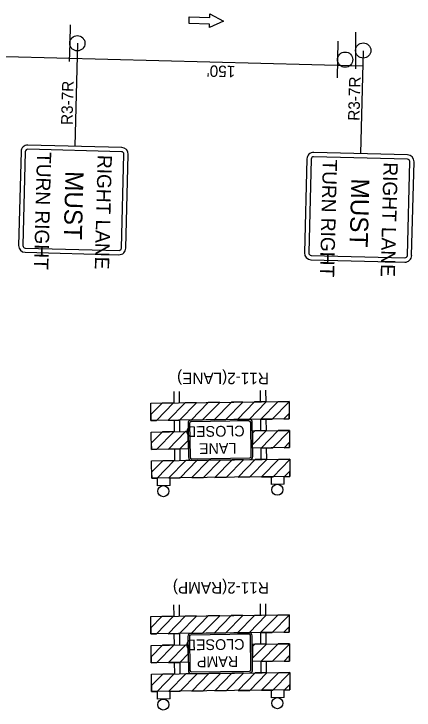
# Model space of a CAD drawing. Extents: x 2135767 to 2151731, y 141839 to 175894.
# Drawn here: x 2150438.8 to 2150648.7, y 145249 to 145614 of the extents above; entities that cross this region are included whole.
import ezdxf

# ---------------------------------------------------------------- set-up
doc = ezdxf.new("R2010")
doc.units = 0
for name, color, linetype in [('PR_Dimensions_Phase1', 7, 'Continuous'), ('PR_Phasing_Detour_1', 7, 'Continuous'), ('PR_Phasing_Traffic_Control_Devices_1', 7, 'Continuous'), ('Pr_Traffic_Arrows_Phase_1', 7, 'Continuous'), ('PR_Txt_Phase_1', 7, 'Continuous')]:
    doc.layers.add(name, color=color, linetype=linetype)

msp = doc.modelspace()

# ---------------------------------------------------------------- linework, layer by layer
at = {"layer": 'PR_Dimensions_Phase1'}
for p, q in [((2150472.1, 145598.57), (2150470.77, 145544.59)), ((2150622.05, 145594.7), (2150620.72, 145540.72))]:
    msp.add_line(p, q, dxfattribs=at)
msp.add_lwpolyline([(2150621.85, 145586.62), (2150300.64, 145594.91), (2150294.97, 145605.06), (2150288.79, 145585.47), (2150285.1, 145595.31), (2150279.06, 145595.47), (2150241.43, 145596.44)], dxfattribs=at)
at = {"layer": 'PR_Phasing_Detour_1'}
for p, q in [((2150608.74, 145599.72), (2150608.56, 145590.07)), ((2150608.56, 145590.07), (2150608.38, 145580.43))]:
    msp.add_line(p, q, dxfattribs=at)
msp.add_circle((2150612.56, 145590), 4, dxfattribs=at)
at = {"layer": 'PR_Phasing_Traffic_Control_Devices_1'}
for p, q in [((2150468.34, 145608.32), (2150468.1, 145598.67)), ((2150618.06, 145604.45), (2150618.06, 145594.8)), ((2150468.1, 145598.67), (2150467.86, 145589.03)), ((2150618.06, 145594.8), (2150618.06, 145585.15)), ((2150442.56, 145541.8), (2150441.29, 145492.6)), ((2150495.31, 145541.71), (2150446.11, 145542.98)), ((2150495.37, 145543.96), (2150446.16, 145545.23)), ((2150444.81, 145541.74), (2150443.54, 145492.54)), ((2150495.27, 145491.21), (2150496.54, 145540.41)), ((2150497.52, 145491.15), (2150498.79, 145540.35)), ((2150645.26, 145537.84), (2150596.06, 145539.11)), ((2150645.32, 145540.08), (2150596.11, 145541.35)), ((2150592.51, 145537.93), (2150591.24, 145488.73)), ((2150594.76, 145537.87), (2150593.49, 145488.67)), ((2150645.22, 145487.34), (2150646.49, 145536.54)), ((2150647.47, 145487.28), (2150648.74, 145536.48)), ((2150444.77, 145491.24), (2150493.97, 145489.97)), ((2150444.71, 145489), (2150493.91, 145487.72)), ((2150594.72, 145487.37), (2150643.92, 145486.1)), ((2150594.66, 145485.12), (2150643.86, 145483.85)), ((2150562.29, 145401.38), (2150531.72, 145401.01)), ((2150562.3, 145400.54), (2150531.73, 145400.17)), ((2150563.26, 145381.89), (2150563.04, 145399.81)), ((2150564.1, 145381.9), (2150563.89, 145399.82)), ((2150530.15, 145399.41), (2150530.37, 145381.49)), ((2150531, 145399.42), (2150531.21, 145381.5)), ((2150531.96, 145380.77), (2150562.53, 145381.14)), ((2150531.97, 145379.93), (2150562.54, 145380.3)), ((2150514.15, 145366.59), (2150514.1, 145370.61)), ((2150520.85, 145366.68), (2150520.8, 145370.69)), ((2150573.97, 145367.31), (2150573.93, 145371.33)), ((2150580.68, 145367.4), (2150580.63, 145371.41)), ((2150520.85, 145366.68), (2150514.15, 145366.59)), ((2150580.68, 145367.4), (2150573.97, 145367.31)), ((2150530.12, 145287.57), (2150530.34, 145269.68)), ((2150530.97, 145287.58), (2150531.18, 145269.69)), ((2150562.22, 145289.54), (2150531.68, 145289.17)), ((2150562.23, 145288.7), (2150531.69, 145288.33)), ((2150563.19, 145270.07), (2150562.97, 145287.97)), ((2150564.03, 145270.08), (2150563.82, 145287.98)), ((2150531.93, 145268.96), (2150562.46, 145269.32)), ((2150531.94, 145268.11), (2150562.47, 145268.48)), ((2150514.12, 145254.72), (2150514.07, 145258.74)), ((2150520.82, 145254.8), (2150520.77, 145258.82)), ((2150573.94, 145255.44), (2150573.89, 145259.46)), ((2150580.65, 145255.52), (2150580.6, 145259.54)), ((2150520.82, 145254.8), (2150514.12, 145254.72)), ((2150580.65, 145255.52), (2150573.94, 145255.44))]:
    msp.add_line(p, q, dxfattribs=at)
for points in [[(2150522.64, 145416.05), (2150522.71, 145410.01)], [(2150525.74, 145410.04), (2150525.66, 145416.09)], [(2150567.97, 145416.6), (2150568.05, 145410.55)], [(2150571.07, 145410.59), (2150571, 145416.63)], [(2150522.82, 145400.94), (2150522.9, 145394.9)], [(2150525.92, 145394.93), (2150525.85, 145400.98)], [(2150568.16, 145401.48), (2150568.23, 145395.44)], [(2150571.25, 145395.48), (2150571.18, 145401.52)], [(2150523.01, 145385.83), (2150523.08, 145379.78)], [(2150526.1, 145379.82), (2150526.03, 145385.87)], [(2150568.34, 145386.37), (2150568.41, 145380.33)], [(2150571.43, 145380.37), (2150571.36, 145386.41)], [(2150567.94, 145304.72), (2150568.02, 145298.68)], [(2150571.04, 145298.71), (2150570.97, 145304.76)], [(2150522.61, 145304.18), (2150522.68, 145298.13)], [(2150525.71, 145298.17), (2150525.63, 145304.21)], [(2150522.79, 145289.07), (2150522.87, 145283.02)], [(2150525.89, 145283.06), (2150525.82, 145289.1)], [(2150568.12, 145289.61), (2150568.2, 145283.57)], [(2150571.22, 145283.6), (2150571.15, 145289.65)], [(2150522.98, 145273.96), (2150523.05, 145267.91)], [(2150526.07, 145267.95), (2150526, 145273.99)], [(2150568.31, 145274.5), (2150568.38, 145268.46)], [(2150571.4, 145268.49), (2150571.33, 145274.54)]]:
    msp.add_lwpolyline(points, dxfattribs=at)
for points in [[(2150583.27, 145401.67), (2150510.74, 145400.79), (2150510.63, 145409.86), (2150583.16, 145410.73)], [(2150558.91, 145410.44), (2150552.89, 145410.37), (2150543.93, 145401.19), (2150549.96, 145401.27)], [(2150571.15, 145410.59), (2150565.05, 145410.52), (2150556.09, 145401.34), (2150562.19, 145401.41)], [(2150583.16, 145410.55), (2150583.16, 145410.73), (2150577.24, 145410.66), (2150568.29, 145401.49), (2150574.38, 145401.56)], [(2150522.56, 145410), (2150516.54, 145409.93), (2150510.7, 145403.95), (2150510.74, 145400.79), (2150513.6, 145400.83)], [(2150534.68, 145410.15), (2150528.65, 145410.08), (2150519.7, 145400.9), (2150525.72, 145400.97)], [(2150546.79, 145410.3), (2150540.77, 145410.22), (2150531.82, 145401.05), (2150537.84, 145401.12)], [(2150580.4, 145401.63), (2150583.27, 145401.67), (2150583.23, 145404.53)], [(2150530.32, 145385.92), (2150510.92, 145385.68), (2150510.81, 145394.75), (2150530.21, 145394.98)], [(2150522.74, 145394.89), (2150516.72, 145394.82), (2150510.88, 145388.84), (2150510.92, 145385.68), (2150513.78, 145385.72)], [(2150530.26, 145390.33), (2150530.21, 145394.98), (2150528.84, 145394.97), (2150519.88, 145385.79), (2150525.9, 145385.86)], [(2150583.45, 145386.56), (2150564.05, 145386.32), (2150563.94, 145395.39), (2150583.34, 145395.62)], [(2150571.33, 145395.48), (2150565.23, 145395.4), (2150563.96, 145394.1), (2150564.03, 145388)], [(2150583.34, 145395.44), (2150583.34, 145395.62), (2150577.42, 145395.55), (2150568.47, 145386.38), (2150574.57, 145386.45)], [(2150580.59, 145386.52), (2150583.45, 145386.56), (2150583.41, 145389.42)], [(2150583.63, 145371.45), (2150511.1, 145370.57), (2150510.99, 145379.64), (2150583.52, 145380.51)], [(2150522.92, 145379.78), (2150516.9, 145379.71), (2150511.06, 145373.73), (2150511.1, 145370.57), (2150513.96, 145370.61)], [(2150535.04, 145379.93), (2150529.02, 145379.86), (2150520.06, 145370.68), (2150526.08, 145370.75)], [(2150547.16, 145380.07), (2150541.14, 145380), (2150532.18, 145370.83), (2150538.2, 145370.9)], [(2150559.28, 145380.22), (2150553.26, 145380.15), (2150544.3, 145370.97), (2150550.32, 145371.04)], [(2150571.51, 145380.37), (2150565.41, 145380.29), (2150556.45, 145371.12), (2150562.55, 145371.19)], [(2150583.52, 145380.33), (2150583.52, 145380.51), (2150577.61, 145380.44), (2150568.65, 145371.27), (2150574.75, 145371.34)], [(2150580.77, 145371.41), (2150583.63, 145371.45), (2150583.6, 145374.31)], [(2150583.24, 145289.79), (2150510.7, 145288.92), (2150510.6, 145297.99), (2150583.13, 145298.86)], [(2150522.53, 145298.13), (2150516.5, 145298.06), (2150510.67, 145292.08), (2150510.7, 145288.92), (2150513.57, 145288.96)], [(2150534.65, 145298.28), (2150528.62, 145298.2), (2150519.67, 145289.03), (2150525.69, 145289.1)], [(2150546.76, 145298.42), (2150540.74, 145298.35), (2150531.78, 145289.17), (2150537.81, 145289.25)], [(2150558.88, 145298.57), (2150552.86, 145298.5), (2150543.9, 145289.32), (2150549.93, 145289.39)], [(2150571.11, 145298.72), (2150565.02, 145298.64), (2150556.06, 145289.47), (2150562.16, 145289.54)], [(2150583.13, 145298.68), (2150583.13, 145298.86), (2150577.21, 145298.79), (2150568.25, 145289.61), (2150574.35, 145289.69)], [(2150580.37, 145289.76), (2150583.24, 145289.79), (2150583.2, 145292.66)], [(2150530.29, 145274.04), (2150510.89, 145273.81), (2150510.78, 145282.88), (2150530.18, 145283.11)], [(2150522.71, 145283.02), (2150516.69, 145282.95), (2150510.85, 145276.97), (2150510.89, 145273.81), (2150513.75, 145273.84)], [(2150530.23, 145278.46), (2150530.18, 145283.11), (2150528.81, 145283.09), (2150519.85, 145273.92), (2150525.87, 145273.99)], [(2150583.42, 145274.68), (2150564.02, 145274.45), (2150563.91, 145283.52), (2150583.31, 145283.75)], [(2150571.3, 145283.6), (2150565.2, 145283.53), (2150563.92, 145282.23), (2150564, 145276.13)], [(2150583.31, 145283.57), (2150583.31, 145283.75), (2150577.39, 145283.68), (2150568.44, 145274.5), (2150574.54, 145274.58)], [(2150580.56, 145274.65), (2150583.42, 145274.68), (2150583.38, 145277.55)], [(2150583.6, 145259.57), (2150511.07, 145258.7), (2150510.96, 145267.77), (2150583.49, 145268.64)], [(2150535.01, 145268.06), (2150528.99, 145267.98), (2150520.03, 145258.81), (2150526.05, 145258.88)], [(2150547.13, 145268.2), (2150541.11, 145268.13), (2150532.15, 145258.95), (2150538.17, 145259.03)], [(2150559.25, 145268.35), (2150553.22, 145268.27), (2150544.27, 145259.1), (2150550.29, 145259.17)], [(2150571.48, 145268.49), (2150565.38, 145268.42), (2150556.42, 145259.25), (2150562.52, 145259.32)], [(2150583.49, 145268.45), (2150583.49, 145268.64), (2150577.58, 145268.57), (2150568.62, 145259.39), (2150574.72, 145259.47)], [(2150522.89, 145267.91), (2150516.87, 145267.84), (2150511.03, 145261.86), (2150511.07, 145258.7), (2150513.93, 145258.73)], [(2150580.74, 145259.54), (2150583.6, 145259.57), (2150583.56, 145262.43)]]:
    msp.add_lwpolyline(points, close=True, dxfattribs=at)
for centre, radius in [((2150472.1, 145598.57), 4), ((2150622.06, 145594.8), 4), ((2150517.22, 145363.75), 2.9), ((2150577.04, 145364.47), 2.9), ((2150517.18, 145251.88), 2.9), ((2150577.01, 145252.6), 2.9)]:
    msp.add_circle(centre, radius, dxfattribs=at)
for centre, radius, start, end in [((2150446.07, 145541.71), 3.52, 88.5212, 178.5212), ((2150446.07, 145541.71), 1.27, 88.5212, 178.5212), ((2150495.28, 145540.44), 3.52, 358.5212, 88.5212), ((2150495.28, 145540.44), 1.27, 358.5212, 88.5212), ((2150596.02, 145537.84), 3.52, 88.5212, 178.5212), ((2150596.02, 145537.84), 1.27, 88.5212, 178.5212), ((2150645.23, 145536.57), 3.52, 358.5212, 88.5212), ((2150645.23, 145536.57), 1.27, 358.5212, 88.5212), ((2150444.8, 145492.51), 3.52, 178.5212, 268.5212), ((2150444.8, 145492.51), 1.27, 178.5212, 268.5212), ((2150494.01, 145491.24), 3.52, 268.5212, 358.5212), ((2150494.01, 145491.24), 1.27, 268.5212, 358.5212), ((2150594.75, 145488.64), 3.52, 178.5212, 268.5212), ((2150594.75, 145488.64), 1.27, 178.5212, 268.5212), ((2150643.96, 145487.37), 3.52, 268.5212, 358.5212), ((2150643.96, 145487.37), 1.27, 268.5212, 358.5212), ((2150531.74, 145399.43), 1.58, 90.6895, 180.6895), ((2150531.74, 145399.43), 0.738, 90.6895, 180.6895), ((2150562.31, 145399.8), 1.58, 0.6895, 90.6895), ((2150562.31, 145399.8), 0.738, 0.6895, 90.6895), ((2150531.95, 145381.51), 1.58, 180.6895, 270.6895), ((2150531.95, 145381.51), 0.738, 180.6895, 270.6895), ((2150562.52, 145381.88), 0.738, 270.6895, 0.6895), ((2150562.52, 145381.88), 1.58, 270.6895, 0.6895), ((2150531.7, 145287.59), 1.58, 90.6895, 180.6895), ((2150531.7, 145287.59), 0.737, 90.6895, 180.6895), ((2150562.24, 145287.96), 1.58, 0.6895, 90.6895), ((2150562.24, 145287.96), 0.737, 0.6895, 90.6895), ((2150531.92, 145269.69), 1.58, 180.6895, 270.6895), ((2150531.92, 145269.69), 0.737, 180.6895, 270.6895), ((2150562.45, 145270.06), 0.737, 270.6895, 0.6895), ((2150562.45, 145270.06), 1.58, 270.6895, 0.6895)]:
    msp.add_arc(centre, radius, start, end, dxfattribs=at)
at = {"layer": 'Pr_Traffic_Arrows_Phase_1'}
for p, q in [((2150530.71, 145608.87), (2150530.81, 145612.47)), ((2150530.81, 145612.47), (2150541.6, 145612.17)), ((2150541.6, 145612.17), (2150541.66, 145613.97)), ((2150541.66, 145613.97), (2150548.75, 145610.17)), ((2150541.5, 145608.57), (2150530.71, 145608.87)), ((2150548.75, 145610.17), (2150541.45, 145606.77)), ((2150541.45, 145606.77), (2150541.5, 145608.57))]:
    msp.add_line(p, q, dxfattribs=at)

# ---------------------------------------------------------------- texts
at = {"layer": 'PR_Phasing_Traffic_Control_Devices_1'}
for s, height, rotation, p in [('TURN RIGHT', 7.485, 268.5212, (2150450.96, 145541.62)), ('RIGHT LANE', 7.485, 268.5212, (2150482.79, 145540.12)), ('TURN RIGHT', 7.485, 268.5212, (2150600.91, 145537.75)), ('RIGHT LANE', 7.485, 268.5212, (2150632.74, 145536.25)), ('MUST', 9.503, 268.5212, (2150465.89, 145531.64)), ('MUST', 9.503, 268.5212, (2150615.84, 145527.76)), ('CLOSED', 5.622, 180.6895, (2150559.83, 145398.12)), ('LANE', 5.622, 180.6895, (2150555.51, 145389.07)), ('CLOSED', 5.616, 180.6895, (2150559.76, 145286.28)), ('RAMP', 5.616, 180.6895, (2150556.45, 145277.26))]:
    msp.add_text(s, height=height, rotation=rotation, dxfattribs=at).set_placement(p)
at = {"layer": 'PR_Txt_Phase_1'}
for s, rotation, p in [("150'", 178.5212, (2150554.99, 145586.68)), ('R3-7R', 88.5859, (2150469.56, 145555.68)), ('R3-7R', 88.5859, (2150620.09, 145557.88)), ('R11-2(LANE)', 179.9496, (2150572.58, 145425.83)), ('R11-2(RAMP)', 179.9496, (2150572.58, 145316.02))]:
    msp.add_text(s, height=6, rotation=rotation, dxfattribs=at).set_placement(p)

doc.saveas('drawing.dxf')
